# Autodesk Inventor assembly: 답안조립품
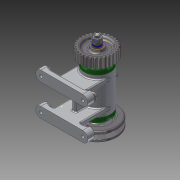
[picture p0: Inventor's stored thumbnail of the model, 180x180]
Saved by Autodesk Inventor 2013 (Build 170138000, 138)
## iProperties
Created: 2015-11
Part Number: 답안조립품
Document SubType Name: Assembly
Designer: Administrator
Author: Administrator
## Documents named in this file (16)
- C:\Users\Administrator\Desktop\451110V1051\답안조립품.iam
- C:\Users\Administrator\Desktop\451110V1051\451110V1051.ipt
- C:\Users\Administrator\Desktop\451110V1051\V벨트풀리.ipt
- C:\Users\Administrator\Desktop\451110V1051\너트 M 8.ipt
- C:\Users\Administrator\Desktop\451110V1051\니플 M 6 x 0.75.ipt
- C:\Users\Administrator\Desktop\451110V1051\베어링 15 x 32 x 9.ipt
- C:\Users\Administrator\Desktop\451110V1051\볼트 M 6 x 8.ipt
- C:\Users\Administrator\Desktop\451110V1051\볼트 M4 x 12.ipt
- C:\Users\Administrator\Desktop\451110V1051\스퍼기어.ipt
- C:\Users\Administrator\Desktop\451110V1051\스프링와셔 8.ipt
- C:\Users\Administrator\Desktop\451110V1051\오일 실 15 25 7.ipt
- C:\Users\Administrator\Desktop\451110V1051\와셔 6x11.5.ipt
- C:\Users\Administrator\Desktop\451110V1051\와셔 8x17.ipt
- C:\Users\Administrator\Desktop\451110V1051\축.ipt
- C:\Users\Administrator\Desktop\451110V1051\커버.ipt
- C:\Users\Administrator\Desktop\451110V1051\키 3 x 3 x 12.ipt
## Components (12 placed, 4 different names)
1. 451110V1051:1
2. V벨트풀리:1
3. KS B 2023 6002 - 15 x 32 x 9:1
4. KS B 2023 6002 - 15 x 32 x 9:2
5. ISO 4762 M4 x 12:1
6. ISO 4762 M4 x 12:3
7. ISO 4762 M4 x 12:4
8. ISO 4762 M4 x 12:5
9. ISO 4762 M4 x 12:2
10. ISO 4762 M4 x 12:6
11. ISO 4762 M4 x 12:7
12. ISO 4762 M4 x 12:8
